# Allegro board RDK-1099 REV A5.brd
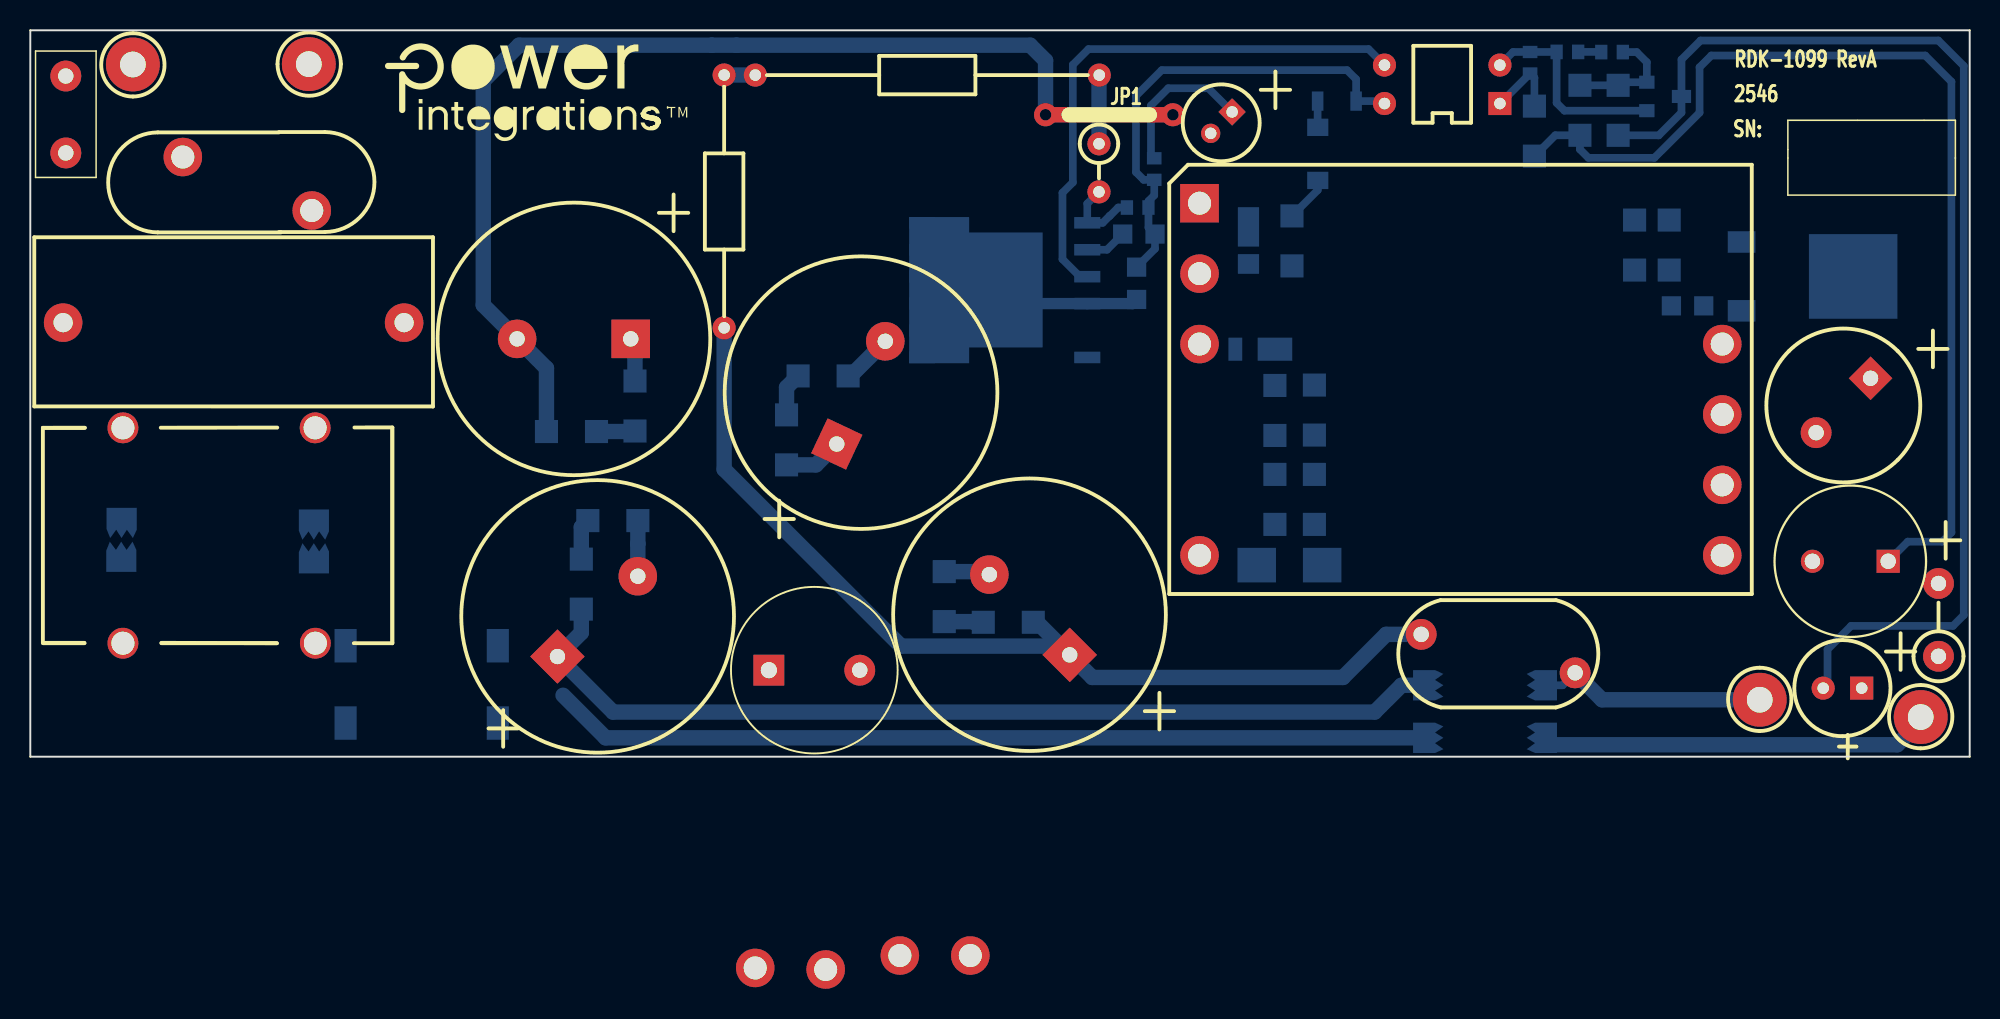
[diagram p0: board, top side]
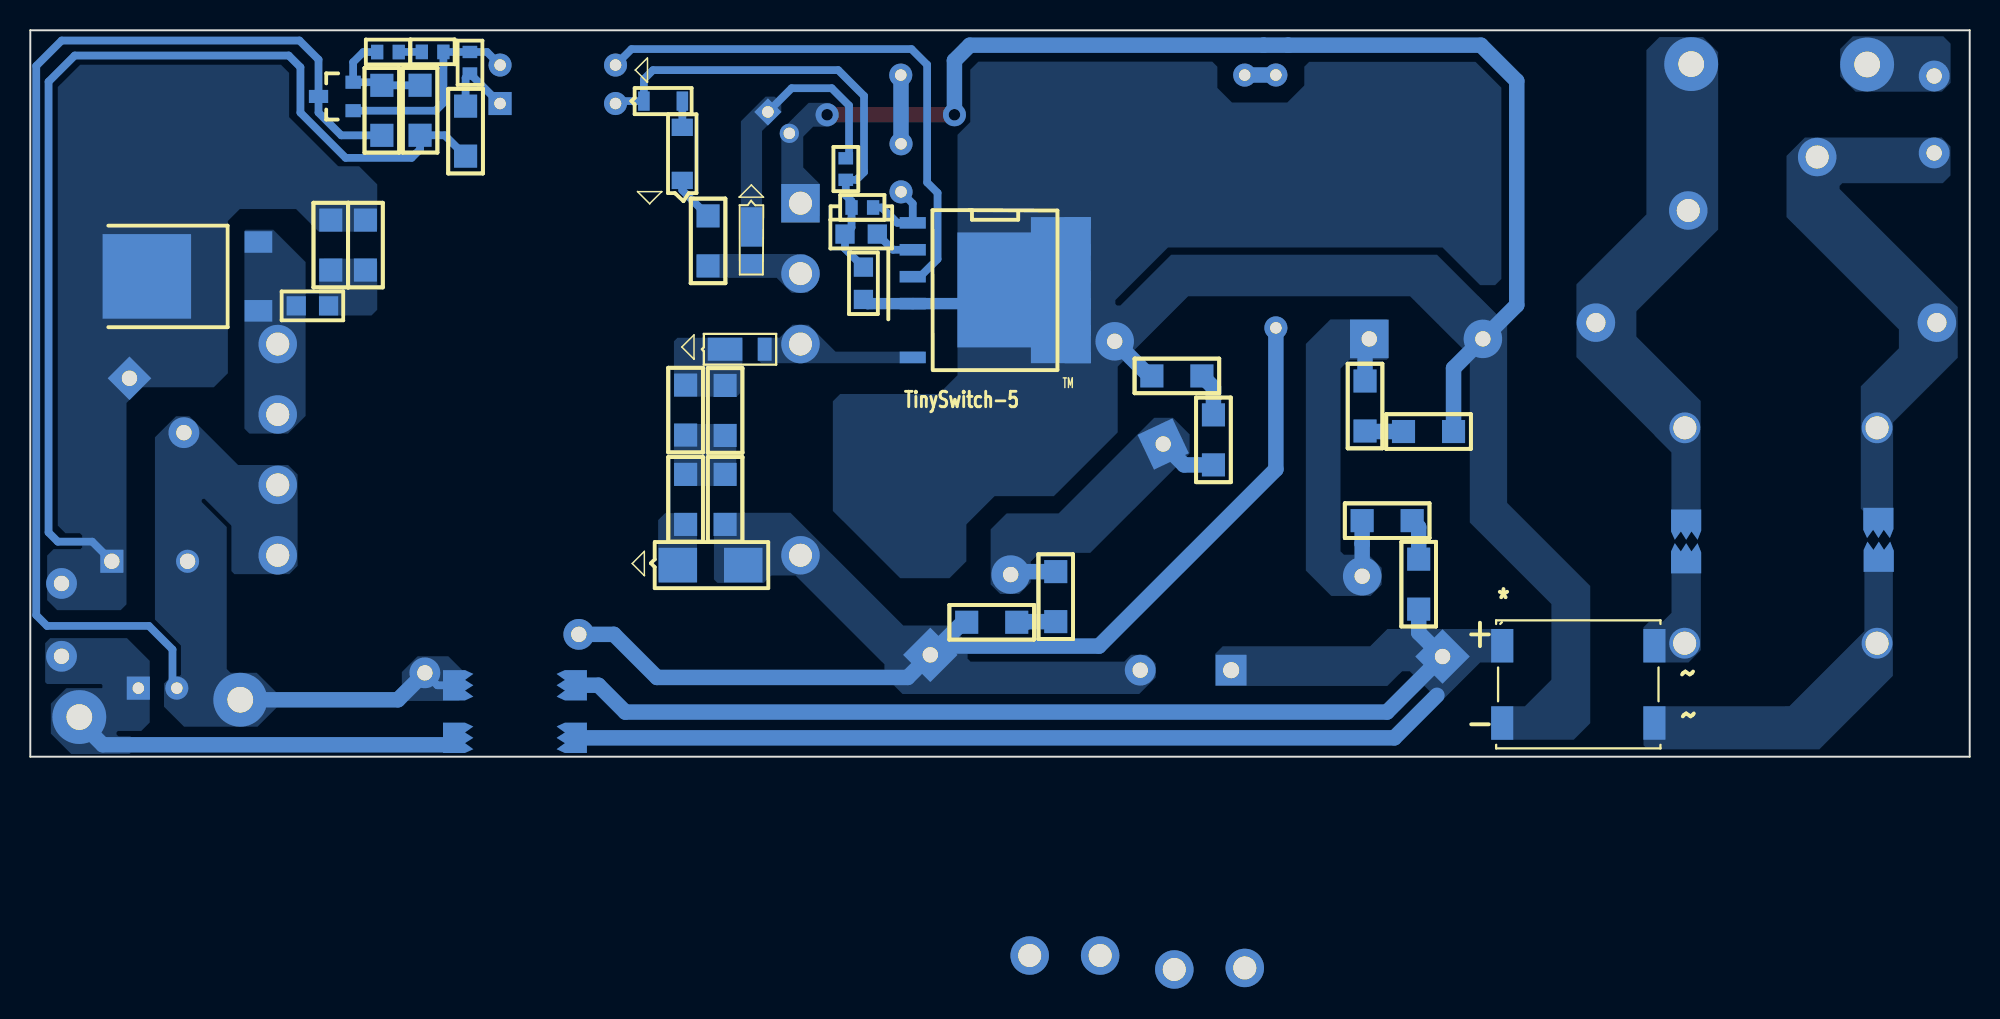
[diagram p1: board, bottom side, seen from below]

Outline 128 x 47.97 mm; copper layers: TOP, BOTTOM. Coordinates in mm from the lower left corner of the outline.
Outline path: 0,47.97 0,0 128,0 128,47.97 0,47.97

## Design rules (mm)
constraint set DEFAULT: min track width 0.508

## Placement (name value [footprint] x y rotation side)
BR1  CD-DF410S  [CD-DF4XXS_BRN]  25.83 4.78 180 bottom
C1  100 nF  [PI_NPCAP1043X433LS886D050]  2.17 28.66 0 top
C2  100 uF  [PIPOLCAPCLYD18LS7P5MMD040]  37.44 9.27 45 top
C3  100 uF  [PIPOLCAPCLYD18LS7P5MMD040]  35.88 27.59 180 top
C4  100 uF  [PIPOLCAPCLYD18LS7P5MMD040]  65.95 9.37 135 top
C5  100 uF  [PIPOLCAPCLYD18LS7P5MMD040]  54.83 24.04 64.7 top
C6  4700 pF  [PISMC1206]  82.14 15.34 90 bottom
C7  47 uF  [PIPOLCAPCLYD200LS80030]  79.32 42.58 225 top
C8  0.47 uF  [PISMC0805]  73.02 32.33 270 bottom
C9  2.2 nF  [PINPYCAPRAD540X290LS400040]  91.8 8.08 0 top
C10  0.033 uF  [PISMC0603]  103.69 46.53 0 bottom
C11  220 pF  [PISMC0805]  110.45 29.77 180 bottom
C12  820 uF  [PIPOLCAPCYLD400LS200040]  121.46 24.99 225 top
C13  820 uF  [PIPOLCAPCLYD10MM040]  122.62 12.9 180 top
C14  100 uF  [PIPOLCAPCYLD250LS100030]  120.87 4.53 180 top
D1  DFLR1600-7  [PISMDDFLR120012]  82.17 26.91 0 bottom
D2  SS10200HE_R1_00001  [PI_SM_SOD-123HE]  80.4 34.99 270 bottom
D3  BAV19WS  [PISMSOD323]  87.51 43.29 180 bottom
D4  STPST10H100SB-TR  [PI_SM_TO252_DPAK]  112.95 29.49 0 bottom
F1  2 A  [PI_RST_MICROFUSE]  2.34 44.95 270 top
GND  BLK  [PITPKEYSTONE125X125]  114.14 3.76 180 top
L  BLK  [PITPKEYSTONE125X125]  6.77 45.71 0 top
L1  10 mH  [PI_TOROID_BALUN_1]  18.81 7.49 90 top
L2  12 uH  [PI_CHOKE_COILCRAFT_RFB1010]  51.75 5.71 0 top
L3  80 ohm  [PISMR0805]  74.23 34.51 180 bottom
L4  Ferrite Bead (3.5 x 7.6 mm)  [PI12WRESD180LS675D040]  125.94 6.63 90 top
N  WHT  [PITPKEYSTONE125X125]  18.38 45.74 90 top
NOREF  -  []  0 47.97 0 top
NOREF#2  -  []  -81.06 -188.87 0 top
NOREF#3  -  []  23.41 -2.92 0 top
NOREF#4  -  []  0 0 90 top
NOREF#5  -  []  45.28 -85.34 0 top
R1  10 M  [PISMR1206]  36.37 9.74 90 bottom
R2  10 M  [PISMR1206]  36.8 15.59 0 bottom
R3  10 M  [PISMR1206]  39.91 24.81 270 bottom
R4  10 M  [PISMR1206]  37.37 21.47 180 bottom
R5  10 M  [PISMR1206]  66.2 8.88 180 bottom
R6  10 M  [PISMR1206]  60.32 8.92 90 bottom
R7  10 M  [PISMR1206]  49.91 19.27 90 bottom
R8  10 M  [PISMR1206]  50.68 25.15 0 bottom
R9  4.02 M  [PI14WRESD100LS400D030#2]  45.79 30.32 90 top
R10  4.02 M  [PI14WRESD100LS400D030]  52.85 45.01 0 top
R11  4.02 M  [PI14WRESD100LS400D030#3]  70.53 40.47 270 top
R12  845 k  [PISMR0603]  72.38 36.27 0 bottom
R13  3 k  [PISMR1206]  84.75 15.34 90 bottom
R14  100  [PISMR1206]  84.75 21.24 90 bottom
R15  100  [PISMR1206]  82.14 21.21 90 bottom
R16  270  [PISMR1206]  83.27 35.71 270 bottom
R17  10.2 k  [PISMR0603]  74.18 38.1 90 bottom
R18  470  [PISMR1206]  99.27 42.96 270 bottom
R19  1 k  [PISMR0603]  98.99 45.12 90 bottom
R20  20 k  [PISMR0603]  100.74 46.54 0 bottom
R21  38.3 k  [PISMR1206]  102.28 41.04 90 bottom
R22  10.0 k  [PISMR1206]  104.8 44.34 270 bottom
R23  100  [PISMR1206]  105.88 32.14 90 bottom
R24  100  [PISMR1206]  108.17 32.14 90 bottom
RV1  460 Vac  [PIDISC675X225LS335X140040]  10.07 39.6 0 top
SG1  5.5mm gap  [PI_SPARK_GAP_5P5MM]  96.01 4.72 0 bottom
SG2  5.5mm gap  [PI_SPARK_GAP_5P5MM]  96.01 1.24 0 bottom
T1  EF25  [PI_BOBBIN_EF25_H_12P]  77.17 36.55 0 top
U1  TNY5094K  [PI_IC_SMD_ESOP_11-12P_SHORT7-12]  69.76 35.26 270 bottom
U2  LTV817D  [PI_DIP4]  97 43.13 90 top
U3  TL431CDBZR  [PISMSOT23123_1]  106.69 44.54 90 bottom
UNK+12V  RED  [PITPKEYSTONE125X125]  124.77 2.62 180 top
VR1  BZG03C150-HM3-08  [PISMDO214AC12]  85.26 12.65 180 bottom
VR2  MMSZ5241C-E3-08  [PI_SM_SOD-123_12]  84.97 38.06 90 bottom

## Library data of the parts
BR1 = DIODE BRIDGE_+~~-
C1 C9 C11 = CAP NP
C2-C5 = CAP POL: alternate symbols: (pipolcapclyd18ls7p5h25mmd040)
C6 = CAP NP: tolerance: 20
C7 = CAP POL: alternate symbols: (pipolcapclyd200ls80030h)
C8 = CAP NP: alternate symbols: (Unisem_RMCF0805UL)
C10 = CAP NP: alternate symbols: (Unisem_RMCF0603UL,pismc0603_1)
C12 C13 = CAP POL: alternate symbols: (pipolcapcyld400ls2000401000h)
C14 = CAP POL: alternate symbols: (pipolcapcyld250ls100030h)
D1 D3 = DIODE
D2 = DIODE SCHOTTKY
D4 = DIODE SCHOTTKY_DPAK_AKA
F1 = FUSE: alternate symbols: (pirstmicrofusehoz)
GND L N = TESTPOINT
L1 = TORRID 4P_12_34
L2 = INDUCTOR
L3 = INDUCTOR_BEAD_2
L4 = INDUCTOR: alternate symbols: (pi12wvresd180ls150d040,pi12wvresd180ls200d040,pi12wvresd180ls250d040); tolerance: 0.1
R1-R8 R13-R16 R21-R24 = R
R9-R11 = R: alternate symbols: (pi14wvresd100ls125d030,pi14wvresd100ls150d030,pi14wvresd100ls200d030,pi14wvresd100ls300d030,pi14wresd100ls400d030,pi14wresd100ls500d030)
R12 R17 R19 R20 = R: alternate symbols: (Unisem_RMCF0603UL)
R18 = R: tolerance: 5%
RV1 = VARISTOR
SG1 SG2 = SPARK_GAP
T1 = BEI30_12P/GENERIC
U1 = TinySwitch-5K
U2 = OPTO_A_B
U3 = TL431CDBZR
UNK+12V = TESTPOINT: alternate symbols: (TP_5010-14)
VR1 VR2 = DIODE_ZENER

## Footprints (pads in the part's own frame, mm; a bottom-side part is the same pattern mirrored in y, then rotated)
CD-DF4XXS_BRN
  rect 1.46x2.21 smd: 1(-5.023,2.553) 2(5.023,2.553) 3(5.023,-2.553) 4(-5.023,-2.553)
PI12WRESD180LS675D040
  round 2.032 hole 1.016: 1(0,0) 2(4.81,0)
PI14WRESD100LS400D030
  round 1.524 hole 0.762: 1(-5,0) 2(17.7,0)
PI14WRESD100LS400D030#2
  round 1.524 hole 0.762: 1(-2,0) 2(14.7,0)
PI14WRESD100LS400D030#3
  round 1.524 hole 0.762: 1(0,0) 2(3.175,0)
PI_BOBBIN_EF25_H_12P
  rect 2.54x2.54 hole 1.524: 1(0,0)
  round 2.54 hole 1.524: 2(0,-4.651) 3(0,-9.301) 4(-29.324,-50.503) 5(-24.674,-50.604) 6(0,-23.251) 7(34.501,-23.251) 8(34.501,-18.6) 9(34.501,-13.95) 10(34.501,-9.301) 11(-15.128,-49.682) 12(-19.779,-49.682)
PI_CHOKE_COILCRAFT_RFB1010
  rect 2.032x2.032 hole 1.067: 1(-3,0)
  round 2.032 hole 1.016: 2(3,0)
PI_DIP4
  rect 1.524x1.524 hole 0.762: 1(0,0)
  round 1.524 hole 0.762: 2(2.54,0) 3(2.54,7.62) 4(0,7.62)
PI_IC_SMD_ESOP_11-12P_SHORT7-12
  rect 0.762x1.727 smd: 1(0,0) 2(1.778,0) 3(3.556,0) 4(5.334,0) 6(8.89,0) 7(8.89,10.897) 8(7.112,10.897) 9(5.334,10.897) 10(3.556,10.897) 11(1.778,10.897) 12(0,10.897)
PI_NPCAP1043X433LS886D050
  round 2.54 hole 1.27: 1(0,0) 2(22.504,0)
PI_RST_MICROFUSE
  round 2.032 hole 1.016: 1(0,0) 2(5.08,0)
PI_SM_SOD-123_12
  rect 1.143x1.397 smd: 1(0,0) 2(3.505,0)
PI_SM_SOD-123HE
  rect 2.6x1.4 smd: 1(0,0)
  rect 1.3x1.4 smd: 2(2.45,0)
PI_SM_TO252_DPAK
  rect 1.829x1.422 smd: 1(0,0) 3(0,-4.445)
  rect 5.842x5.588 smd: 2(7.62,-2.223)
PI_SPARK_GAP_5P5MM
  custom 0.5x0.5 smd: 1(-3.749,0) 2(3.749,0)
PI_TOROID_BALUN_1
  round 2.032 hole 1.524: 1(0,0) 2(14.224,0.013) 3(0,12.7) 4(14.224,12.7)
PIDISC675X225LS335X140040
  round 2.54 hole 1.524: 1(0,0) 2(8.509,-3.531)
PINPYCAPRAD540X290LS400040
  round 2.032 hole 1.016: 1(0,0) 2(10.16,-2.54)
PIPOLCAPCLYD10MM040
  rect 1.524x1.524 hole 1.016: 1(0,0)
  round 1.524 hole 1.016: 2(5,0)
PIPOLCAPCLYD18LS7P5MMD040
  rect 2.54x2.54 hole 1.016: 1(-3.75,0)
  round 2.54 hole 1.016: 2(3.75,0)
PIPOLCAPCLYD200LS80030
  rect 1.27x1.27 hole 0.762: 1(0,0)
  round 1.27 hole 0.762: 2(1.999,0)
PIPOLCAPCYLD250LS100030
  rect 1.524x1.524 hole 0.762: 1(0,0)
  round 1.524 hole 0.762: 2(2.54,0)
PIPOLCAPCYLD400LS200040
  rect 2.032x2.032 hole 1.016: 1(0,0)
  round 2.032 hole 1.016: 2(5.08,0)
PISMC0603
  rect 0.813x0.965 smd: 1(0,0) 2(1.422,0)
PISMC0805
  rect 1.27x1.27 smd: 1(0,0) 2(2.134,0)
PISMC1206
  rect 1.524x1.524 smd: 1(0,0) 2(3.302,0)
PISMDDFLR120012
  rect 2.286x1.524 smd: 1(-0.025,0)
  rect 0.914x1.524 smd: 2(-2.642,0)
PISMDO214AC12
  rect 2.54x2.286 smd: 1(0,0) 2(4.318,0)
PISMR0603
  rect 0.813x0.965 smd: 1(0,0) 2(1.422,0)
PISMR0805
  rect 1.27x1.27 smd: 1(0,0) 2(2.134,0)
PISMR1206
  rect 1.524x1.524 smd: 1(0,0) 2(3.302,0)
PISMSOD323
  rect 0.762x1.27 smd: 1(0,0) 2(2.54,0)
PISMSOT23123_1
  rect 0.864x1.016 smd: 1(-1.88,0) 2(0,0)
  rect 0.864x1.27 smd: 3(-0.94,2.286)
PITPKEYSTONE125X125
  round 3.556 hole 1.702: 1(0,0)

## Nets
N232812: BR1.4 C3.2 C5.2 C7.2 C8.2 R4.2 R8.2 T1.1 U1.4 U1.7 U1.8 U1.9 U1.10 U1.11 U1.12
N233356: C14.1 L4.1 SG2.2 UNK+12V.1
N233758: C6.2 R13.2 R14.1 R15.1
N234018: BR1.1 C2.1 L2.1 R1.1 SG1.1 SG2.1
N234026: C9.2 C12.2 C13.2 C14.2 GND.1 R22.2 SG1.2 T1.7 T1.8 U3.3
N234356: C12.1 C13.1 D4.2 L4.2 R18.2 R21.1 R23.2 R24.2
N234408: C10.2 R21.2 R22.1 U3.2(VREF)
N361695: C7.1 D2.1 R17.2
N9221700: D2.2 R16.2 T1.2
N9273985: C1.1 F1.2 L1.4 RV1.1
N9299708: C4.1 C6.1 C9.1 L2.2 R5.1 R9.1 T1.6 VR1.2
N9317049: C1.2 L1.2 N.1 RV1.2
N9342481: R18.1 R19.1 U2.1
N9436307: C11.2 R23.1 R24.1
N9436321: C11.1 D4.1 D4.3 T1.9 T1.10
N9446382: C10.1 R20.2
N9464475: R19.2 R20.1 U2.2 U3.1
N9467610: BR1.3 L1.3
N9469611: D1.2 T1.3 U1.6
N9474130: F1.1 L.1
N9474318: BR1.2 L1.1
N9474875: D1.1 R14.2 R15.2
N9482891: L3.2 U1.2
N9485927: C8.1 D3.1 L3.1 R12.2 R17.1 U2.4
N9515325: R11.2 R12.1 U1.1
N9531791: R9.2 R10.1
N9533645: U1.3 U2.3(E)
N9537521: R13.1 VR1.1
N9539308: D3.2 VR2.2
N9555264: R16.1 VR2.1
N9562271: C2.2 C3.1 R2.2 R3.1
N9562449: R1.2 R2.1
N9562513: R3.2 R4.1
N9562701: C4.2 C5.1 R6.2 R7.1
N9562746: R5.2 R6.1
N9562772: R7.2 R8.1
N9566319: R10.2 R11.1

Pads without a net: T1 4 5 11 12

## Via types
v1: diameter 1.524, hole 0.762, TOP to BOTTOM, 2 vias

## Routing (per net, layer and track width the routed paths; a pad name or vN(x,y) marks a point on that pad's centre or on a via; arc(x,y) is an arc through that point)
N232812: length 87.7
  TOP w1.016: v1(75.41,42.39) v1(67.01,42.39)
  BOTTOM w0.75: C8.2 72.74,29.92 U1.4 64.16,29.92
  BOTTOM w1.016: C5.2 54.14,25.15 R8.2 ; v1(67.01,42.39) 67.01,45.97 65.99,46.99 46.61,46.99 46.61,46.99 44.98,46.99 44.98,46.99 32.26,46.99 29.9,44.62 29.9,29.82 C3.2 34.07,25.65 R4.2
N233356: length 26.1
  BOTTOM w1.016: SG2.2 100.22,0.79 123.22,0.79 124.77,2.34 UNK+12V.1
N234018: length 121.8
  BOTTOM w1.016: SG2.1 37.97,1.24 35.16,4.06 ; SG1.1 90.5,4.72 88.73,2.95 38.46,2.95 C2.1 36.37,8.19 R1.1
N234026: length 92.5
  BOTTOM w0.508: C14.2 118.62,4.81 118.62,7.08 120.17,8.64 126.9,8.64 127.61,9.35 127.61,45.62 125.93,47.29 110.24,47.29 108.98,46.04 U3.3 108.98,42.54 107.48,41.03 R22.2 ; C9.2 101.14,4.72 SG1.2
  BOTTOM w1.016: C9.2 103.74,3.76 GND.1
N234356: length 69.3
  BOTTOM w0.508: R18.2 100.65,41.04 R21.1 102.28,40.11 102.84,39.55 107.19,39.55 110.17,42.53 110.17,45.53 110.95,46.3 125.07,46.3 126.8,44.58 126.8,14.81 126.19,14.2 123.92,14.2 C13.1
N234408: length 7.7
  BOTTOM w0.508: R21.2 102.28,44.34 R22.1 105,44.54 U3.2 106.69,45.86 106.02,46.53 C10.2
N361695: length 10.1
  BOTTOM w0.508: C7.1 77.75,44.15 75.11,44.15 73.96,43 73.96,39.73 R17.2
N9299708: length 64.7
  BOTTOM w1.016: 68.02,7.3 57.47,7.3 45.79,18.98 R9.1 ; 68.02,7.3 66.45,8.88 R5.1 ; 68.02,7.3 C4.1 70.09,5.23 86.64,5.23 89.48,8.08 C9.1
N9342481: length 5.1
  BOTTOM w0.508: U2.1 97.01,43.13 R19.1 99.27,44.83 R18.1
N9446382: length 1.5
  BOTTOM w0.508: R20.2 103.68,46.54 C10.1
N9464475: length 13.6
  BOTTOM w0.508: U3.1 101.26,42.66 100.74,43.18 R20.1 100.73,46.54 R19.2 97.86,46.54 U2.2
N9482891: length 2.8
  BOTTOM w0.508: U1.2 71.06,33.48 L3.2
N9485927: length 31.9
  BOTTOM w0.508: U2.4 89.22,43.29 D3.1 87.51,44.74 86.91,45.34 74.68,45.34 72.97,43.64 72.97,38.6 73.48,38.1 R17.1 74.18,37.07 73.8,36.69 R12.2 73.8,34.95 L3.1 74.23,33.55 C8.1
N9515325: length 5.4
  BOTTOM w0.508: R11.2 69.76,36.53 U1.1 70.78,35.26 71.23,35.71 71.24,35.71 71.8,36.27 R12.1
N9531791: length 2.1
  BOTTOM w1.016: R9.2 47.85,45.02 R10.1
N9533645: length 36.7
  BOTTOM w0.508: U2.3 88.32,46.73 69.84,46.73 68.81,45.7 68.81,37.92 68.12,37.24 68.12,32.85 69.28,31.7 U1.3
N9539308: length 1.7
  BOTTOM w0.508: VR2.2 84.97,41.57 D3.2
N9555264: length 3
  BOTTOM w0.508: VR2.1 84.97,37.41 R16.1
N9562271: length 6.6
  BOTTOM w1.016: R2.2 40.1,14.07 40.1,14.06 C2.2 ; R3.1 39.91,27.31 C3.1
N9562449: length 2.7
  BOTTOM w1.016: R2.1 36.37,15.16 R1.2
N9562513: length 2.6
  BOTTOM w1.016: R3.2 39.88,21.47 R4.1
N9562701: length 6.9
  BOTTOM w1.016: C4.2 63.1,12.22 R6.2 ; R7.1 51.85,19.27 C5.1
N9562746: length 2.6
  BOTTOM w1.016: R5.2 62.29,8.88 62.24,8.92 R6.1
N9562772: length 2.9
  BOTTOM w1.016: R7.2 49.91,24.38 R8.1
N9566319: length 4.5
  BOTTOM w1.016: R10.2 70.53,44.99 R11.1

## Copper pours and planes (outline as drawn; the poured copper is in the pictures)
N232812 on BOTTOM (solid shape): 61.96,25.98 58,25.98 58,35.64 61.96,35.64
N232812 on BOTTOM (solid shape): 66.81,27.03 61.79,27.03 61.79,34.62 66.81,34.62
N232812 on BOTTOM: 76.35,35.31 78.23,35.31 78.44,35.51 78.44,41.38 76.63,43.18 75.23,43.18 74.7,42.65 74.7,42.16 75.26,41.61 76.33,41.61 76.99,40.94 76.99,38.91 75.9,37.82 75.9,35.76
N232812 on BOTTOM: 49.99,45.9 65.43,45.9 65.96,45.36 65.96,41.91 66.8,41.07 66.8,25.2 68.05,23.95 74.55,23.95 75.03,23.47 75.03,16.23 70.59,11.79 67.34,11.79 66.22,12.9 66.22,15.34 64.35,17.21 60.44,17.21 56.24,21.41 56.24,25.76 51.59,30.4 36.93,30.4 32.99,26.47 32.99,15.47 27.61,10.08 27.61,5.08 29.36,3.33 31.55,3.33 31.55,1.12 26.14,1.12 25.04,2.21 25.04,11.28 30.53,16.76 30.53,28.52 35.15,33.15 52.7,33.15 56.06,29.79 56.29,29.79 56.39,29.9 56.39,30.15 52.91,33.63 34.8,33.63 32.31,31.14 31.32,31.14 30.91,31.55 30.91,44.18 32.61,45.89 43.6,45.89 43.92,45.57 43.92,44.32 45.03,43.21 48.69,43.21 49.66,44.17 49.66,45.57
N233356 on BOTTOM: 121.62,7.82 126.7,7.82 127.03,7.49 127.03,4.93 126.9,4.8 123.32,4.8 123.24,4.72 123.24,4.57 123.29,4.52 125.63,4.52 126.64,3.51 126.64,1.52 125.3,0.18 121.45,0.18 121.25,0.38 121.25,1.19 121.4,1.35 122.19,1.35 122.32,1.47 122.32,1.6 122.21,1.7 120.68,1.7 120.12,2.26 120.12,6.32
N233758 on BOTTOM: 81.51,21.97 85.37,21.97 85.52,21.82 85.52,18.06 85.34,17.88 81.51,17.88 81.41,17.98 81.41,21.87
N234018 on BOTTOM: 37.47,5.64 38.43,4.67 49.81,4.67 49.81,6.78 49.3,7.29 39.57,7.29 38.43,8.43 30.12,8.43 30.12,6.22 32.31,6.22 34.92,3.61 36.96,5.64
N234026 on BOTTOM: 119.78,21.09 119.78,9.06 118.06,7.34 118.06,5.41 118.14,5.33 118.67,5.33 119.18,4.83 119.18,3.3 117.86,1.98 113,1.98 111.66,3.33 111.66,4.14 113.06,5.54 114.78,5.54 115.04,5.79 115.04,15.16 116.69,16.82 116.69,16.95 116.61,17.03 116.5,17.03 115.7,16.23 114.73,15.26 114.73,12.26 114.53,12.05 110.91,12.05 110.36,12.6 110.36,18.64 110.98,19.26 114.28,19.26 117.5,22.48 118.39,22.48
N234026 on BOTTOM: 102.44,6.63 100.41,6.63 99.47,5.69 99.47,3.94 99.72,3.68 103.35,3.68 103.48,3.81 103.48,5.59
N234356 on BOTTOM: 120.61,24.4 121.65,23.35 121.65,10.06 122.04,9.68 126.23,9.68 126.89,10.34 126.89,13.28 126.47,13.7 124.69,13.7 124.58,13.82 124.58,14.61 124.73,14.76 125.68,14.76 126.19,15.27 126.19,44.22 124.71,45.69 111.46,45.69 110.92,45.16 110.92,42.24 107.67,38.99 106.3,38.99 105.11,37.8 105.11,34.82 105.26,34.67 108.97,34.67 110.46,36.16 114.18,36.16 114.96,35.38 114.96,25.32 115.89,24.4
N361695 on BOTTOM: 78.87,43.59 79.48,43.59 81.1,41.96 81.1,33.93 80.87,33.71 79.91,33.71 79.71,33.91 79.71,41.33 78.44,42.6 78.44,43.15
N9221700 on BOTTOM: 76.86,33.2 83.87,33.2 84.02,33.05 84.02,31.72 83.92,31.62 78.74,31.62 77.75,30.63 76.71,30.63 76.15,31.19 76.15,32.49
N9273985 on BOTTOM (solid shape): 7.03,14.99 6.77,14.44 6.37,14.99 6.02,14.44 5.67,14.99 5.27,14.44 5.03,15.04 5.03,16.44 7.03,16.44
N9273985 on BOTTOM: 6.88,16.08 5.33,16.08 5.05,16.36 5.05,22.07 0.79,26.34 0.79,29.69 8.59,37.49 8.59,37.69 8.41,37.87 1.78,37.87 1.27,38.38 1.27,40.31 1.85,40.89 10.87,40.89 12.09,39.67 12.09,35.64 4.67,28.22 4.67,26.97 7.19,24.46 7.19,16.38
N9299708 on BOTTOM: 77.5,11.96 79.1,11.96 79.58,11.48 82.65,11.48 82.88,11.71 82.88,15.9 82.68,16.1 77.83,16.1 70.38,8.66 67.31,8.66 66.14,7.49 66.14,6.48 65.94,6.27 55.8,6.27 55.35,6.73 54.31,6.73 53.72,6.15 53.72,5.23 54.81,4.14 70.43,4.14 71.63,5.33 71.63,6.1
N9317049 on BOTTOM (solid shape): 19.71,14.87 19.46,14.32 19.06,14.87 18.71,14.32 18.36,14.87 17.96,14.32 17.72,14.93 17.72,16.32 19.71,16.32
N9317049 on BOTTOM: 25.96,26.39 20.8,21.23 20.8,21.21 19.68,20.09 19.68,16.1 19.43,15.85 18.01,15.85 17.75,16.1 17.75,23.5 22,27.74 22,29.41 16.6,34.81 16.6,46.52 17.6,47.52 20.47,47.52 21.34,46.66 21.34,35.81 25.96,31.19
N9436307 on BOTTOM: 105.31,32.89 108.66,32.89 108.94,32.61 108.94,29.29 108.79,29.13 105.49,29.13 105.11,29.51 105.11,32.69
N9436321 on BOTTOM: 113.54,21.34 111,21.34 109.83,22.5 109.83,32.66 111.96,34.8 113.79,34.8 113.87,34.72 113.87,21.67
N9467610 on BOTTOM (solid shape): 7,13.66 7,12.2 5.01,12.2 5.01,13.6 5.25,14.2 5.65,13.66 6,14.2 6.35,13.66 6.75,14.2
N9467610 on BOTTOM: 21.53,3.33 12.21,3.33 12.2,3.34 11.89,3.34 6.95,8.28 6.95,12.88 6.88,12.95 5.2,12.95 5.07,12.83 5.07,5.33 9.92,0.48 21.26,0.48 21.53,0.75
N9469611 on BOTTOM: 69.01,25.98 68.94,26.06 68.94,26.67 69.01,26.75 74.85,26.75 76.63,28.52 77.7,28.52 78.56,27.66 79.98,27.66 79.98,26.21 79.76,25.98
N9474130 on BOTTOM: 7.71,47.57 1.74,47.57 1.26,47.09 1.26,44.5 1.84,43.92 7.53,43.92 8.55,44.93 8.55,46.74
N9474318 on BOTTOM (solid shape): 19.71,13.55 19.71,12.1 17.72,12.1 17.72,13.5 17.96,14.1 18.36,13.55 18.71,14.1 19.07,13.55 19.46,14.1
N9474318 on BOTTOM: 21.53,6.22 18.56,6.22 17.75,7.04 17.75,12.29 17.85,12.4 19.55,12.4 19.68,12.27 19.68,9.5 20.25,8.92 21.15,8.92 21.53,8.54
N9474875 on BOTTOM: 81.18,27.66 85.29,27.66 85.52,27.43 85.52,23.93 85.37,23.77 81.38,23.77 81,24.16 81,27.48
N9537521 on BOTTOM: 84.15,16.08 86.11,16.08 86.56,15.62 86.56,11.68 86.39,11.51 84.18,11.51 84,11.68 84,15.93
N9562271 on BOTTOM: 38.53,28.88 42.19,28.88 43.81,27.25 43.81,12.29 42.14,10.62 39.55,10.62 38.81,11.35 38.81,12.47 39.67,13.34 41.3,13.34 41.53,13.56 41.53,25.63 40.94,26.21 38.48,26.21 38.35,26.34 38.35,28.7
N9562701 on BOTTOM: 58.04,13.46 61.39,13.46 61.98,12.88 61.98,11.51 62.74,10.74 63.98,10.74 64.62,11.38 64.62,15.01 63.56,16.07 60.13,16.07 53.82,22.38 52.58,22.38 51.49,21.29 51.49,20.02

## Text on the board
Ref Des/Silkscreen Bottom: TM | TinySwitch-5
Ref Des/Silkscreen Top: JP1 | SN: | 2546 | RDK-1099 RevA | +
User.10: FIGURE | FINISHED_SIZE | 30.0 | 40.0 | 42.0 | 50.0 | 60.0 | 67.0 | DRILL CHART: TOP to BOTTOM | ALL UNITS ARE IN MILS | TOLERANCE_DRILL | +3.0/-3.0 | PLATED | QTY | 16 | 19 | 1 | 2 | 18 | 4 | 60 | TOTAL HOLES:
